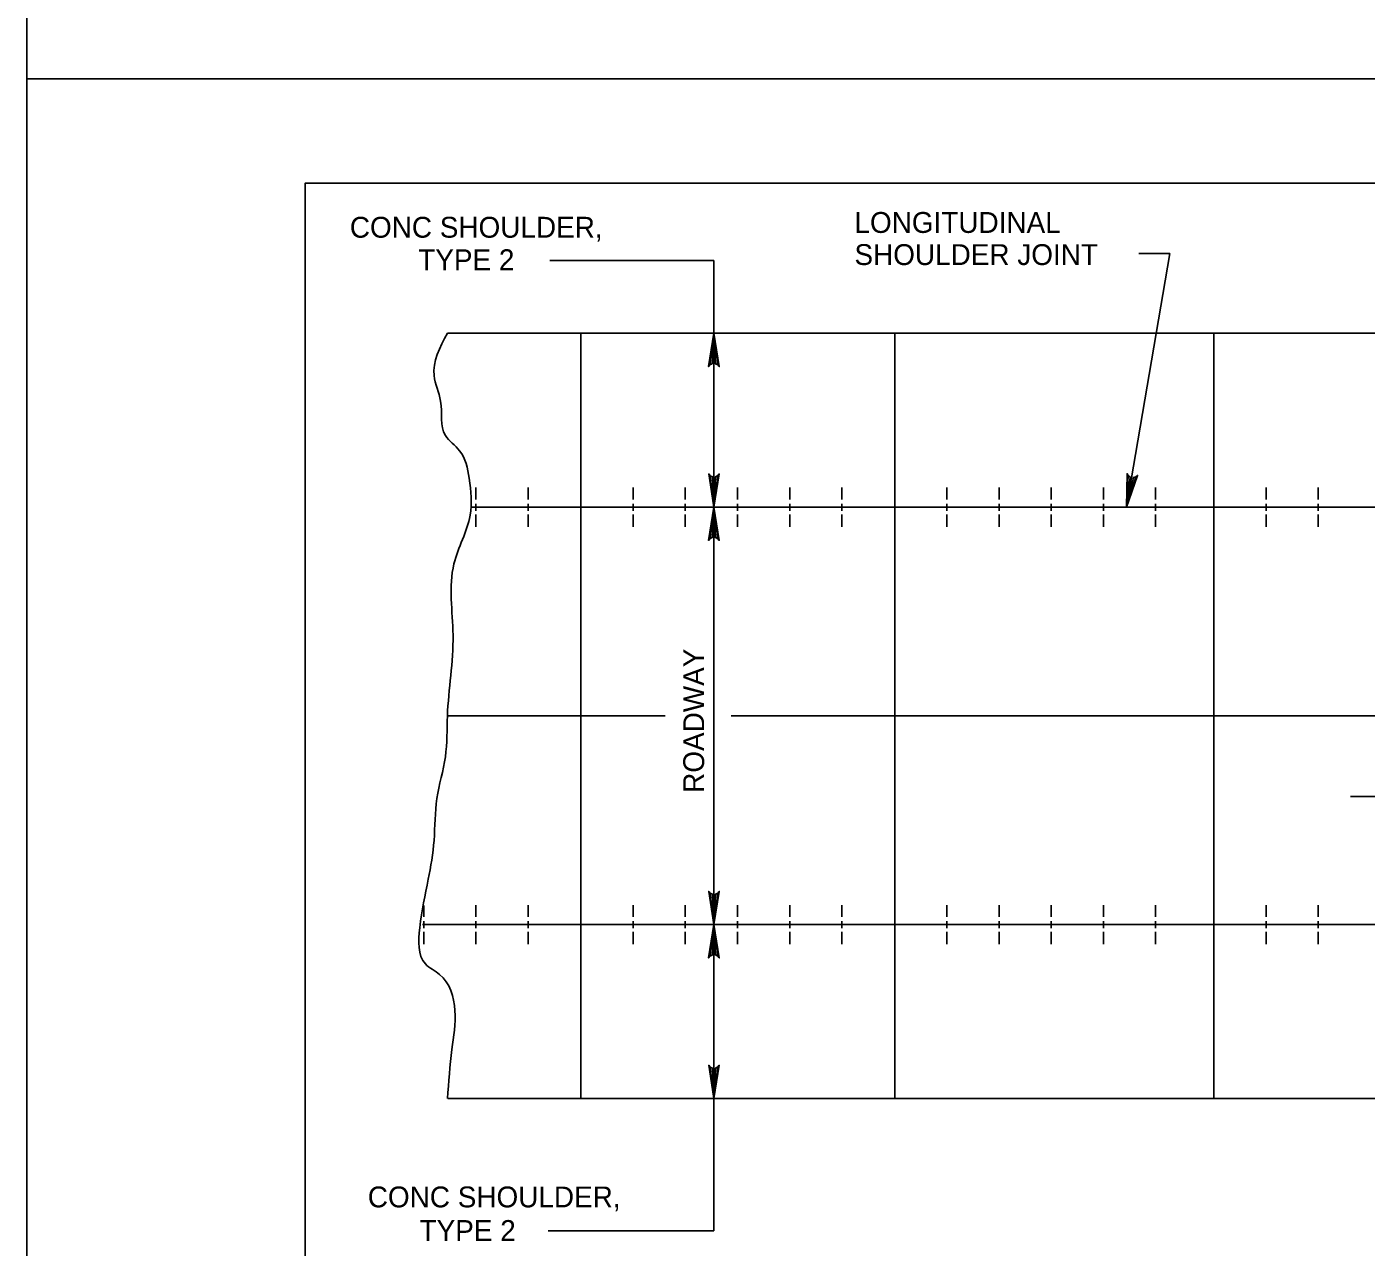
# Model space of a CAD drawing. Extents: x 638216 to 639962, y 297510 to 299292.
# Drawn here: x 638215.9 to 638408.4, y 297936.3 to 298111.7 of the extents above; entities that cross this region are included whole.
import ezdxf

# ---------------------------------------------------------------- set-up
doc = ezdxf.new("R2010")
doc.units = 0
for name, color, linetype in [('1', 7, 'Continuous'), ('2', 7, 'Continuous'), ('3', 7, 'Continuous'), ('PLT-BNDY', 7, 'Continuous')]:
    doc.layers.add(name, color=color, linetype=linetype)

msp = doc.modelspace()

# ---------------------------------------------------------------- linework, layer by layer
at = {"layer": '1'}
msp.add_lwpolyline([(639041.88, 297525.24), (639041.88, 298089.24), (638255.88, 298089.24), (638255.88, 297525.24), (639041.88, 297525.24), (639041.88, 297551.6), (638841.88, 297551.6), (638841.88, 297616.28), (639041.88, 297616.28), (639041.88, 297645.24), (638841.88, 297645.24), (638841.88, 297525.24), (638920.69, 297525.24), (638920.69, 297551.6), (638920.69, 297525.24), (638997.69, 297525.24), (638997.69, 297551.6), (638997.69, 297539.28), (639041.88, 297539.28)], dxfattribs=at)
msp.add_lwpolyline([(639041.88, 297525.24), (639041.88, 298089.24), (638255.88, 298089.24), (638255.88, 297525.24), (639041.88, 297525.24), (639041.88, 297551.6), (638841.88, 297551.6), (638841.88, 297616.28), (639041.88, 297616.28), (639041.88, 297645.24), (638841.88, 297645.24), (638841.88, 297525.24), (638920.69, 297525.24), (638920.69, 297551.6), (638920.69, 297525.24), (638997.69, 297525.24), (638997.69, 297551.6), (638997.69, 297539.28), (639041.88, 297539.28)], dxfattribs=at)
msp.add_lwpolyline([(639041.88, 297525.24), (639041.88, 298089.24), (638255.88, 298089.24), (638255.88, 297525.24), (639041.88, 297525.24), (639041.88, 297551.6), (638841.88, 297551.6), (638841.88, 297616.28), (639041.88, 297616.28), (639041.88, 297645.24), (638841.88, 297645.24), (638841.88, 297525.24), (638920.69, 297525.24), (638920.69, 297551.6), (638920.69, 297525.24), (638997.69, 297525.24), (638997.69, 297551.6), (638997.69, 297539.28), (639041.88, 297539.28)], dxfattribs=at)
at = {"layer": '2'}
for p, q in [((638291.03, 298078.15), (638314.63, 298078.15)), ((638314.63, 298067.68), (638314.63, 298078.15)), ((638380.17, 298079.16), (638373.95, 298042.68)), ((638375.69, 298079.16), (638380.17, 298079.16)), ((638276.33, 298067.68), (638576.33, 298067.68)), ((638295.52, 297957.68), (638295.52, 298067.68)), ((638314.63, 298042.68), (638314.63, 298067.68)), ((638340.61, 297957.68), (638340.61, 298067.68)), ((638386.49, 297957.68), (638386.49, 298067.68)), ((638280.43, 298043.79), (638280.43, 298045.49)), ((638287.93, 298043.79), (638287.93, 298045.49)), ((638303.02, 298043.79), (638303.02, 298045.49)), ((638310.52, 298043.79), (638310.52, 298045.49)), ((638318.02, 298043.79), (638318.02, 298045.49)), ((638325.52, 298043.79), (638325.52, 298045.49)), ((638333.02, 298043.79), (638333.02, 298045.49)), ((638348.11, 298043.79), (638348.11, 298045.49)), ((638355.61, 298043.79), (638355.61, 298045.49)), ((638363.11, 298043.79), (638363.11, 298045.49)), ((638370.61, 298043.79), (638370.61, 298045.49)), ((638378.11, 298043.79), (638378.11, 298045.49)), ((638393.99, 298043.79), (638393.99, 298045.49)), ((638401.49, 298043.79), (638401.49, 298045.49)), ((638279.72, 298042.68), (638579.3, 298042.68)), ((638280.43, 298042.18), (638280.43, 298043.15)), ((638280.43, 298039.87), (638280.43, 298041.64)), ((638287.93, 298042.18), (638287.93, 298043.15)), ((638287.93, 298039.87), (638287.93, 298041.64)), ((638303.02, 298042.18), (638303.02, 298043.15)), ((638303.02, 298039.87), (638303.02, 298041.64)), ((638310.52, 298042.18), (638310.52, 298043.15)), ((638310.52, 298039.87), (638310.52, 298041.64)), ((638314.63, 297982.67), (638314.63, 298042.68)), ((638318.02, 298042.18), (638318.02, 298043.15)), ((638318.02, 298039.87), (638318.02, 298041.64)), ((638325.52, 298042.18), (638325.52, 298043.15)), ((638325.52, 298039.87), (638325.52, 298041.64)), ((638333.02, 298042.18), (638333.02, 298043.15)), ((638333.02, 298039.87), (638333.02, 298041.64)), ((638348.11, 298042.18), (638348.11, 298043.15)), ((638348.11, 298039.87), (638348.11, 298041.64)), ((638355.61, 298042.18), (638355.61, 298043.15)), ((638355.61, 298039.87), (638355.61, 298041.64)), ((638363.11, 298042.18), (638363.11, 298043.15)), ((638363.11, 298039.87), (638363.11, 298041.64)), ((638370.61, 298042.18), (638370.61, 298043.15)), ((638370.61, 298039.87), (638370.61, 298041.64)), ((638378.11, 298042.18), (638378.11, 298043.15)), ((638378.11, 298039.87), (638378.11, 298041.64)), ((638393.99, 298042.18), (638393.99, 298043.15)), ((638393.99, 298039.87), (638393.99, 298041.64)), ((638401.49, 298042.18), (638401.49, 298043.15)), ((638401.49, 298039.87), (638401.49, 298041.64)), ((638276.33, 298012.68), (638307.64, 298012.68)), ((638317.13, 298012.68), (638579.51, 298012.68)), ((638406.14, 298001.07), (638423.99, 298001.07)), ((638272.93, 297983.79), (638272.93, 297985.41)), ((638280.43, 297983.79), (638280.43, 297985.49)), ((638287.93, 297983.79), (638287.93, 297985.49)), ((638303.02, 297983.79), (638303.02, 297985.49)), ((638310.52, 297983.79), (638310.52, 297985.49)), ((638318.02, 297983.79), (638318.02, 297985.49)), ((638325.52, 297983.79), (638325.52, 297985.49)), ((638333.02, 297983.79), (638333.02, 297985.49)), ((638348.11, 297983.79), (638348.11, 297985.49)), ((638355.61, 297983.79), (638355.61, 297985.49)), ((638363.11, 297983.79), (638363.11, 297985.49)), ((638370.61, 297983.79), (638370.61, 297985.49)), ((638378.11, 297983.79), (638378.11, 297985.49)), ((638393.99, 297983.79), (638393.99, 297985.49)), ((638401.49, 297983.79), (638401.49, 297985.49)), ((638272.76, 297982.68), (638577.2, 297982.68)), ((638272.93, 297982.18), (638272.93, 297983.15)), ((638276.33, 297982.68), (638576.33, 297982.68)), ((638280.43, 297982.18), (638280.43, 297983.15)), ((638287.93, 297982.18), (638287.93, 297983.15)), ((638303.02, 297982.18), (638303.02, 297983.15)), ((638310.52, 297982.18), (638310.52, 297983.15)), ((638314.63, 297957.67), (638314.63, 297982.67)), ((638318.02, 297982.18), (638318.02, 297983.15)), ((638325.52, 297982.18), (638325.52, 297983.15)), ((638333.02, 297982.18), (638333.02, 297983.15)), ((638348.11, 297982.18), (638348.11, 297983.15)), ((638355.61, 297982.18), (638355.61, 297983.15)), ((638363.11, 297982.18), (638363.11, 297983.15)), ((638370.61, 297982.18), (638370.61, 297983.15)), ((638378.11, 297982.18), (638378.11, 297983.15)), ((638393.99, 297982.18), (638393.99, 297983.15)), ((638401.49, 297982.18), (638401.49, 297983.15)), ((638272.93, 297979.87), (638272.93, 297981.64)), ((638280.43, 297979.87), (638280.43, 297981.64)), ((638287.93, 297979.87), (638287.93, 297981.64)), ((638303.02, 297979.87), (638303.02, 297981.64)), ((638310.52, 297979.87), (638310.52, 297981.64)), ((638318.02, 297979.87), (638318.02, 297981.64)), ((638325.52, 297979.87), (638325.52, 297981.64)), ((638333.02, 297979.87), (638333.02, 297981.64)), ((638348.11, 297979.87), (638348.11, 297981.64)), ((638355.61, 297979.87), (638355.61, 297981.64)), ((638363.11, 297979.87), (638363.11, 297981.64)), ((638370.61, 297979.87), (638370.61, 297981.64)), ((638378.11, 297979.87), (638378.11, 297981.64)), ((638393.99, 297979.87), (638393.99, 297981.64)), ((638401.49, 297979.87), (638401.49, 297981.64)), ((638276.4, 297957.68), (638576.33, 297957.68)), ((638314.63, 297938.66), (638314.63, 297957.67)), ((638290.79, 297938.66), (638314.63, 297938.66))]:
    msp.add_line(p, q, dxfattribs=at)
for points in [[(638314.06, 298063.14), (638314.39, 298063.31), (638314.63, 298067.68), (638314.06, 298063.14), (638313.87, 298062.9), (638314.63, 298067.68), (638314.85, 298063.31), (638315.18, 298063.15), (638314.63, 298067.68), (638315.39, 298062.9), (638315.18, 298063.15)], [(638315.2, 298047.22), (638314.88, 298047.05), (638314.63, 298042.68), (638315.2, 298047.22), (638315.4, 298047.46), (638314.63, 298042.68), (638314.42, 298047.05), (638314.09, 298047.21), (638314.63, 298042.68), (638313.88, 298047.46), (638314.09, 298047.21)], [(638375.27, 298047.06), (638374.92, 298046.95), (638373.95, 298042.68), (638375.27, 298047.06), (638375.51, 298047.26), (638373.95, 298042.68), (638374.47, 298047.02), (638374.17, 298047.24), (638373.95, 298042.68), (638374, 298047.51), (638374.17, 298047.24)], [(638314.06, 298038.14), (638314.39, 298038.31), (638314.63, 298042.68), (638314.06, 298038.14), (638313.87, 298037.91), (638314.63, 298042.68), (638314.85, 298038.31), (638315.18, 298038.15), (638314.63, 298042.68), (638315.39, 298037.91), (638315.18, 298038.15)], [(638315.2, 297987.22), (638314.88, 297987.05), (638314.63, 297982.67), (638315.2, 297987.22), (638315.4, 297987.45), (638314.63, 297982.67), (638314.42, 297987.04), (638314.09, 297987.2), (638314.63, 297982.67), (638313.88, 297987.45), (638314.09, 297987.2)], [(638314.06, 297978.14), (638314.39, 297978.3), (638314.63, 297982.67), (638314.06, 297978.14), (638313.87, 297977.9), (638314.63, 297982.67), (638314.85, 297978.31), (638315.18, 297978.15), (638314.63, 297982.67), (638315.39, 297977.9), (638315.18, 297978.15)], [(638315.2, 297962.22), (638314.88, 297962.05), (638314.63, 297957.67), (638315.2, 297962.22), (638315.4, 297962.45), (638314.63, 297957.67), (638314.42, 297962.04), (638314.09, 297962.2), (638314.63, 297957.67), (638313.88, 297962.45), (638314.09, 297962.2)]]:
    msp.add_lwpolyline(points, dxfattribs=at)
msp.add_spline([(638276.33, 298067.68), (638274.41, 298061.59), (638275.36, 298057.91), (638276.04, 298052.99), (638278.09, 298050.8), (638279.45, 298046.83), (638279.6, 298041.52), (638277.28, 298034.55), (638277.14, 298024.3), (638276.33, 298012.68), (638276.04, 298006.81), (638274.82, 298000.8), (638274.41, 297994.79), (638273.58, 297989.19), (638272.36, 297982.22), (638273.17, 297977.03), (638275.22, 297975.52), (638277.41, 297970.34), (638276.99, 297964.74), (638276.33, 297957.68)], degree=3, dxfattribs=at)
at = {"layer": 'PLT-BNDY'}
for points in [[(638215.88, 298698.24), (639056.88, 298698.24), (639056.88, 298104.24), (638215.88, 298104.24)], [(638215.88, 298104.24), (639056.88, 298104.24), (639056.88, 297510.24), (638215.88, 297510.24)]]:
    msp.add_lwpolyline(points, close=True, dxfattribs=at)

# ---------------------------------------------------------------- texts
at = {"layer": '3'}
for s, p in [('CONC SHOULDER,', (638262.31, 298081.42)), ('LONGITUDINAL', (638334.83, 298082.11)), ('SHOULDER JOINT', (638334.83, 298077.49)), ('TYPE 2', (638272.14, 298076.75)), ('CONC SHOULDER,', (638264.89, 297942.03)), ('TYPE 2', (638272.33, 297937.2))]:
    msp.add_text(s, height=3, dxfattribs=at).set_placement(p)
msp.add_text('ROADWAY', height=3, rotation=90, dxfattribs=at).set_placement((638313.23, 298001.62))

doc.saveas('drawing.dxf')
